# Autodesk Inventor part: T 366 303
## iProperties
Created: 2005-10
Part Number: T 366 303
Material: 1.0570
Description: Rohrtraverse
Vendor: Autodesk Inc.
Document SubType Name: Modeling
Standard: DIN 59 411
Designer: I.Baliuc
Size Designation: 120 x 80 x 6.3 - 410
Density: 7.84 g/cm^3
G_L: 410,000 mm
Zweck: Trenner 3-polig
Rohabmessung: 120 x 80 x 6,3
Author: T.Messerschmitt
Revision Number: 366303
Comments: Hohlprofil DIN 59 411 - ersetzt durch DIN EN 10219-2 120 x 80 x 6.3 - 410
Keywords: 381136
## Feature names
1. Körper [Extrusion]
2. Rundung1 [Fillet]
3. Rundung2 [Fillet]
4. Bohrung1 [Hole]
5. Extrusion2
6. Fase1 [Chamfer]
